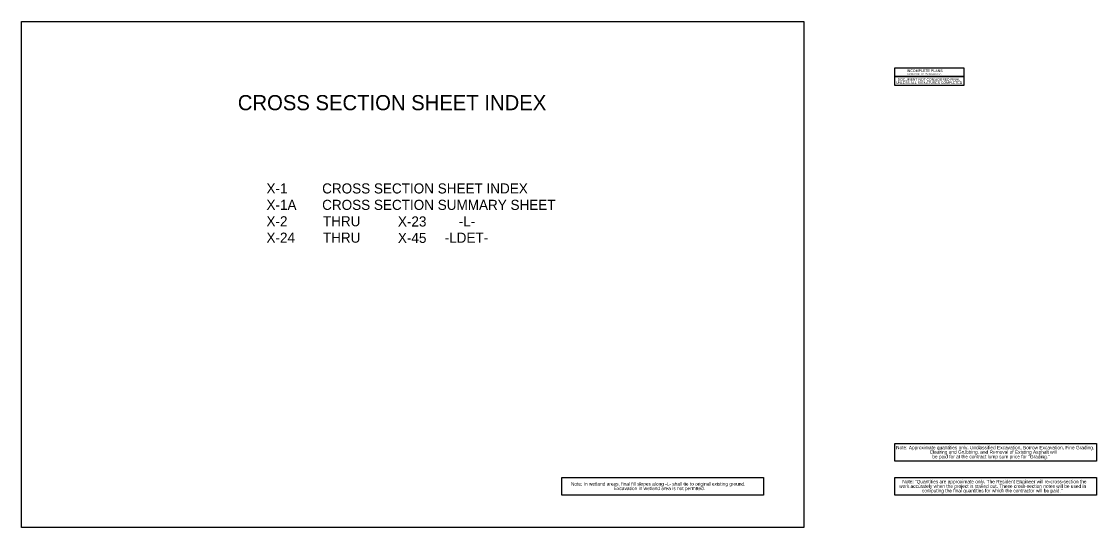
# Model space of a CAD drawing. Extents: x 24 to 7314, y 15 to 1598.
# Drawn here: x 24 to 2360, y 15 to 1115 of the extents above; entities that cross this region are included whole.
import ezdxf

# ---------------------------------------------------------------- set-up
doc = ezdxf.new("R2010")
doc.units = 0
for name, color, linetype in [('Default', 7, 'Continuous'), ('Sheet Title CELL', 7, 'Continuous'), ('Sheet_Data_Field_CELL', 7, 'Continuous')]:
    doc.layers.add(name, color=color, linetype=linetype)

msp = doc.modelspace()

# ---------------------------------------------------------------- linework, layer by layer
at = {"layer": 'Default'}
msp.add_lwpolyline([(24, 1115), (1724, 1115), (1724, 15), (24, 15)], close=True, dxfattribs=at)
at = {"layer": 'Sheet Title CELL'}
for points in [[(1921.6, 197.5), (2360, 197.5), (2360, 159), (1921.6, 159)], [(1197.8, 123.4), (1636.2, 123.4), (1636.2, 85), (1197.8, 85)], [(1921.6, 123.4), (2360, 123.4), (2360, 85), (1921.6, 85)]]:
    msp.add_lwpolyline(points, close=True, dxfattribs=at)
at = {"layer": 'Sheet_Data_Field_CELL'}
for points in [[(1921.6, 1014.2), (2071.6, 1014.2), (2071.6, 995.1), (1921.6, 995.1)], [(1921.6, 995.1), (2071.6, 995.1), (2071.6, 976), (1921.6, 976)]]:
    msp.add_lwpolyline(points, close=True, dxfattribs=at)

# ---------------------------------------------------------------- texts
at = {"layer": 'Sheet Title CELL'}
for s, height, p in [('CROSS SECTION SHEET INDEX', 32.926, (494, 922.1)), ('X-1', 21.95, (556.3, 741.1)), ('CROSS SECTION SHEET INDEX', 21.95, (677.3, 741.1)), ('X-1A', 21.95, (556.3, 705.4)), ('CROSS SECTION SUMMARY SHEET', 21.95, (677.3, 705.4)), ('X-2', 21.95, (556.3, 669.7)), ('THRU', 21.95, (678.9, 669.8)), ('X-23', 21.95, (841.9, 669.3)), ('-L-', 21.95, (974.1, 669.6)), ('X-24', 21.95, (556.3, 634.1)), ('THRU', 21.95, (678.9, 634.1)), ('X-45', 21.95, (841.9, 633.6)), ('-LDET-', 21.95, (943.5, 634)), ('Note: Approximate quantities only. Unclassified Excavation, Borrow Excavation, Fine Grading, ', 7.5, (1924.5, 185)), ('   Clearing and Grubbing, and Removal of Existing Asphalt will', 7.5, (1988.8, 175.2)), ('be paid for at the contract lump sum price for "Grading."', 7.5, (2003.1, 165.3)), ('Note: "Quantities are approximate only. The Resident Engineer will re-cross-section the', 7.5, (1938, 111)), ('Note: In wetland areas, final fill slopes along -L- shall tie to original existing ground. ', 7.5, (1217.8, 106)), ('   Excavation in wetland area is not permtted.', 7.5, (1302.7, 96.2)), ('work accurately when the project is staked out. These cross-section notes will be used in', 7.5, (1931.2, 101.1)), ('computing the final quantities for which the contractor will be paid."', 7.5, (1980.7, 91.3))]:
    msp.add_text(s, height=height, dxfattribs=at).set_placement(p)
at = {"layer": 'Sheet_Data_Field_CELL'}
for s, height, p in [('INCOMPLETE PLANS', 5.625, (1947.5, 1005.1)), ('DO NOT USE FOR R/W ACQUISITION', 3.037, (1949.4, 999.5))]:
    msp.add_text(s, height=height, dxfattribs=at).set_placement(p)
for s, p in [('UNLESS ALL SIGNATURES COMPLETED', (1924.2, 979.2)), ('DOCUMENT NOT CONSIDERED FINAL', (1927.8, 986.2))]:
    msp.add_text(s, height=5.4, rotation=0, dxfattribs=at).set_placement(p)

doc.saveas('drawing.dxf')
